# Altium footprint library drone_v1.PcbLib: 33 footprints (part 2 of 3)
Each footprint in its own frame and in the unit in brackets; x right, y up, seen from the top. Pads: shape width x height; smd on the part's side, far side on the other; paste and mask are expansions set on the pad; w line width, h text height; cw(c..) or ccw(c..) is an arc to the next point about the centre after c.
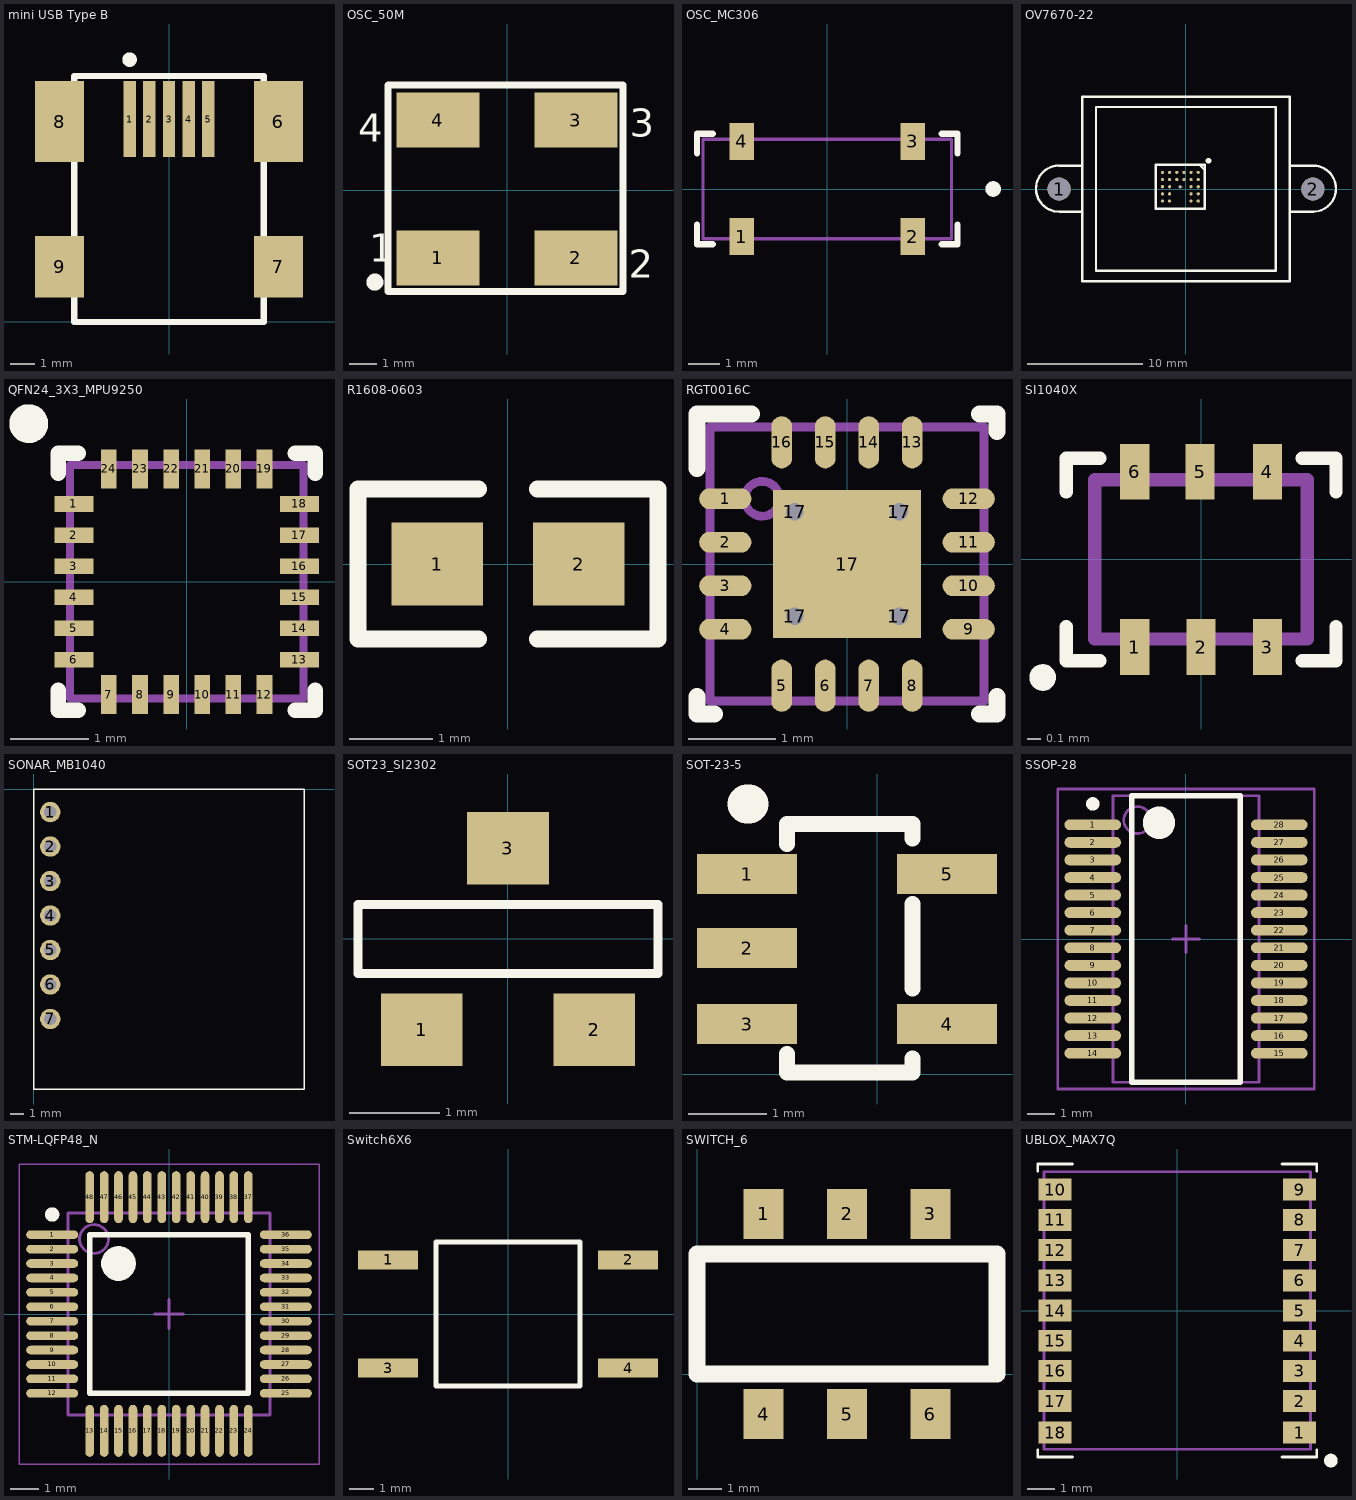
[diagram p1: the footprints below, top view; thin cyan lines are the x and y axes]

## mini USB Type B [mm]
pads (9):
  rect 0.5x3.1 smd: 1(-1.6,8.25) 2(-0.8,8.25) 3(0,8.25) 4(0.8,8.25) 5(1.6,8.25)
  rect 2x3.3 smd: 6(4.45,8.15) 8(-4.45,8.15)
  rect 2x2.5 smd: 7(4.45,2.25) 9(-4.45,2.25)
Top Overlay:
  circle w0.3: c-1.6,10.668 r0.146
  lines w0.254: -3.85,0 -3.85,10 3.85,10 3.85,0 -3.85,0

## OSC_50M [mm] "for 50MHz"
height 3.5
pads (4):
  rect 3x2 smd: 1(-2.515,-2.46) 2(2.489,-2.46) 3(2.485,2.54) 4(-2.515,2.54)
Top Overlay:
  circle w0.5: c-4.801,-3.333 r0.057
  lines w0.254: -4.318,-3.683 -4.318,3.81 4.191,3.81 4.191,-3.683 -4.318,-3.683
  text "1" at -5.004,-2.591 h1.02
  text "2" at 4.394,-3.175 h1.02
  text "3" at 4.445,1.93 h1.02
  text "4" at -5.41,1.753 h1.02

## OSC_MC306 [mm]
pads (4):
  rect 0.8x1.2 smd paste+0 mask+0.05: 1(-2.75,-1.53) 2(2.75,-1.53) 3(2.75,1.53) 4(-2.75,1.53)
Top Overlay:
  circle w0.25: c5.336,0 r0.125
  lines w0.2: -4.191,-1.143 -4.191,-1.778 -3.683,-1.778 ; -4.191,1.143 -4.191,1.778 -3.683,1.778 ; 3.683,-1.778 4.191,-1.778 4.191,-1.143 ; 3.683,1.778 4.191,1.778 4.191,1.143
Mechanical 13:
  lines w0.1: -4,-1.6 -4,1.6 4,1.6 4,-1.6 -4,-1.6

## OV7670-22 [mm]
pads (26):
  round 2 hole 2: 1(-11,0) 2(11,0)
  round 0.28 smd: A1(1.062,1.44) A2(1.062,0.82) A3(1.062,0.2) A4(1.062,-0.42) A5(1.062,-1.04) B1(0.442,1.44) B2(0.442,0.82) B3(0.442,0.2) B4(0.442,-0.42) B5(0.442,-1.04) C1(-0.178,1.44) C2(-0.178,0.82) D1(-0.798,1.44) D2(-0.798,0.82) E1(-1.418,1.44) E2(-1.418,0.82) E3(-1.418,0.2) E4(-1.418,-0.42) E5(-1.418,-1.04) F1(-2.038,1.44) F2(-2.038,0.82) F3(-2.038,0.2) F4(-2.038,-0.42) F5(-2.038,-1.04)
Top Overlay:
  circle w0.25: c1.951,2.454 r0.125
  lines w0.102: -0.632,0.2 -0.327,0.2 ; -0.488,0.068 -0.488,0.347
  lines w0.2: 1.165,2.1 1.637,1.628 ; -2.613,-1.7 1.637,-1.7 1.637,2.1 -2.613,2.1 -2.613,-1.7
  lines w0.203: -9.062,-1.967 -10.977,-1.967 cw(c-11.011,0.032) -11.049,2.032 -9,2.032 ; -7.8,-7.112 -7.8,7.1 ; -7.8,7.112 7.8,7.112 ; -7.788,-7.1 7.788,-7.1 ; 7.8,-7.1 7.8,7.1 ; 9,2.032 11.049,2.032 cw(c11.014,0.032) 11.033,-1.968 9.063,-1.968 ; 9,8 -9,8 -9,-8 9,-8 9,8.001

## QFN24_3X3_MPU9250 [mm]
pads (24):
  rect 0.5x0.2 smd paste+0 mask+0.03: 1(-1.45,1) 2(-1.45,0.6) 3(-1.45,0.2) 4(-1.45,-0.2) 5(-1.45,-0.6) 6(-1.45,-1) 13(1.45,-1) 14(1.45,-0.6) 15(1.45,-0.2) 16(1.45,0.2) 17(1.45,0.6) 18(1.45,1)
  rect 0.2x0.5 smd paste+0 mask+0.03: 7(-1,-1.45) 8(-0.6,-1.45) 9(-0.2,-1.45) 10(0.2,-1.45) 11(0.6,-1.45) 12(1,-1.45) 19(1,1.45) 20(0.6,1.45) 21(0.2,1.45) 22(-0.2,1.45) 23(-0.6,1.45) 24(-1,1.45)
Top Overlay:
  circle w0.25: c-2.03,2.032 r0.125
  lines w0.2: -1.651,-1.397 -1.651,-1.651 -1.397,-1.651 ; -1.651,1.397 -1.651,1.651 -1.397,1.651 ; 1.397,-1.651 1.651,-1.651 1.651,-1.397 ; 1.397,1.651 1.651,1.651 1.651,1.397
Mechanical 13:
  lines w0.1: -1.5,-1.5 0,-1.5 1.5,-1.5 1.5,1.5 -1.5,1.5 -1.5,-1.5

## R1608-0603 [mm]
pads (2):
  rect 1.1x1 smd: 1(-0.85,0) 2(0.85,0)
Top Overlay:
  lines w0.2: -0.35,-0.9 -1.8,-0.9 -1.8,0.9 -0.35,0.9 ; 0.35,-0.9 1.8,-0.9 1.8,0.9 0.35,0.9

## RGT0016C [mm]
pads (21):
  oval 0.6x0.24 smd paste-0.102 mask+0.051: 1(-1.4,0.75) 2(-1.4,0.25) 3(-1.4,-0.25) 4(-1.4,-0.75) 9(1.4,-0.75) 10(1.4,-0.25) 11(1.4,0.25) 12(1.4,0.75)
  oval 0.24x0.6 smd paste-0.102 mask+0.051: 5(-0.75,-1.4) 6(-0.25,-1.4) 7(0.25,-1.4) 8(0.75,-1.4) 13(0.75,1.4) 14(0.25,1.4) 15(-0.25,1.4) 16(-0.75,1.4)
  round 0.5 / inner round 1.524 / far side round 0.5 hole 0.203 mask+0.051: 17(-0.6,-0.6) 17(-0.6,0.6) 17(0.6,-0.6) 17(0.6,0.6)
  rect 1.7x1.7 smd paste-0.837 mask+0.051: 17(0,0)
Top Overlay:
  lines w0.2: -1.725,-1.525 -1.725,-1.725 -1.525,-1.725 ; -1.725,1.1 -1.725,1.725 -1.1,1.725 ; 1.525,-1.725 1.725,-1.725 1.725,-1.525 ; 1.525,1.725 1.725,1.725 1.725,1.525
Top Paste:
  region: -0.774,0.774 -0.774,-0.774 0.774,-0.774 0.774,0.774
Mechanical 1:
  circle w0.1: c-0.975,0.75 r0.2
  lines w0.1: -1.575,-1.575 1.575,-1.575 1.575,1.575 -1.575,1.575 -1.575,-1.575

## SI1040X [mm]
pads (6):
  rect 0.22x0.42 smd paste+0 mask+0.05: 1(-0.5,-0.66) 2(0,-0.66) 3(0.5,-0.66) 4(0.5,0.66) 5(-0.008,0.66) 6(-0.5,0.66)
Top Overlay:
  circle w0.1: c-1.193,-0.889 r0.05
  lines w0.1: -1.016,-0.508 -1.016,-0.762 -0.762,-0.762 ; -1.016,0.508 -1.016,0.762 -0.762,0.762 ; 0.762,-0.762 1.016,-0.762 1.016,-0.508 ; 0.762,0.762 1.016,0.762 1.016,0.508
Mechanical 13:
  lines w0.1: -0.8,-0.6 0.8,-0.6 0.8,0.6 -0.8,0.6 -0.8,-0.6

## SONAR_MB1040 [mm]
pads (7):
  round 1.5 hole 0.9: 1(1.2,-1.7) 2(1.2,-4.24) 3(1.2,-6.78) 4(1.2,-9.32) 5(1.2,-11.86) 6(1.2,-14.4) 7(1.2,-16.94)
Top Overlay:
  lines w0.1: 0,-22.1 19.9,-22.1 19.9,0 0,0 0,-22.1

## SOT23_SI2302 [mm]
pads (3):
  rect 0.9x0.8 smd: 1(-0.95,-1) 2(0.95,-1) 3(0,1)
Top Overlay:
  lines w0.1: -1.651,-0.381 -1.651,0.381 1.651,0.381 1.651,-0.381 -1.651,-0.381

## SOT-23-5 [mil]
pads (5):
  rect 50x20 smd: 1(-65,100) 2(-65,63) 3(-65,25) 4(35,25) 5(35,100)
Top Overlay:
  lines w8: -45,10 -45,0.68 17.76,0.68 17.76,7.76 ; -45,115 -45,125 17.76,125 17.76,117.76 ; 17.76,42.76 17.76,85
  lines w19.68: -65,135 -64,135

## SSOP-28 [mm] "28-Pin SSOP 0.65 mm Pitch"
height 2
pads (28):
  oval 2.1x0.4 smd: 1(-3.45,4.225) 2(-3.45,3.575) 3(-3.45,2.925) 4(-3.45,2.275) 5(-3.45,1.625) 6(-3.45,0.975) 7(-3.45,0.325) 8(-3.45,-0.325) 9(-3.45,-0.975) 10(-3.45,-1.625) 11(-3.45,-2.275) 12(-3.45,-2.925) 13(-3.45,-3.575) 14(-3.45,-4.225) 15(3.45,-4.225) 16(3.45,-3.575) 17(3.45,-2.925) 18(3.45,-2.275) 19(3.45,-1.625) 20(3.45,-0.975) 21(3.45,-0.325) 22(3.45,0.325) 23(3.45,0.975) 24(3.45,1.625) 25(3.45,2.275) 26(3.45,2.925) 27(3.45,3.575) 28(3.45,4.225)
Top Overlay:
  circle w0.25: c-3.45,5 r0.125
  circle w0.6: c-1,4.3 r0.3
  lines w0.2: -2,-5.3 -2,5.3 2,5.3 2,-5.3 -2,-5.3
Mechanical 13:
  circle w0.1: c-1.8,4.4 r0.5
  lines w0.1: -2.7,-5.3 -2.7,5.3 2.7,5.3 2.7,-5.3 -2.7,-5.3
Mechanical 15:
  lines w0.1: -0.5,0 0.5,0 ; 0,-0.5 0,0.5 ; -4.75,-5.55 -4.75,5.55 4.75,5.55 4.75,-5.55 -4.75,-5.55
3D body: height 2, standoff 0, extent -2.7,-5.3 2.7,5.3

## STM-LQFP48_N [mm] "QFP, 48-Leads, Body 7x7mm, Pitch 0.5mm, IPC Medium Density"
height 1.6
pads (48):
  oval 1.8x0.3 smd: 1(-4.05,2.75) 2(-4.05,2.25) 3(-4.05,1.75) 4(-4.05,1.25) 5(-4.05,0.75) 6(-4.05,0.25) 7(-4.05,-0.25) 8(-4.05,-0.75) 9(-4.05,-1.25) 10(-4.05,-1.75) 11(-4.05,-2.25) 12(-4.05,-2.75) 25(4.05,-2.75) 26(4.05,-2.25) 27(4.05,-1.75) 28(4.05,-1.25) 29(4.05,-0.75) 30(4.05,-0.25) 31(4.05,0.25) 32(4.05,0.75) 33(4.05,1.25) 34(4.05,1.75) 35(4.05,2.25) 36(4.05,2.75)
  oval 0.3x1.8 smd: 13(-2.75,-4.05) 14(-2.25,-4.05) 15(-1.75,-4.05) 16(-1.25,-4.05) 17(-0.75,-4.05) 18(-0.25,-4.05) 19(0.25,-4.05) 20(0.75,-4.05) 21(1.25,-4.05) 22(1.75,-4.05) 23(2.25,-4.05) 24(2.75,-4.05) 37(2.75,4.05) 38(2.25,4.05) 39(1.75,4.05) 40(1.25,4.05) 41(0.75,4.05) 42(0.25,4.05) 43(-0.25,4.05) 44(-0.75,4.05) 45(-1.25,4.05) 46(-1.75,4.05) 47(-2.25,4.05) 48(-2.75,4.05)
Top Overlay:
  circle w0.6: c-1.75,1.75 r0.3
  circle w0.25: c-4.05,3.45 r0.125
  lines w0.2: -2.75,-2.75 2.75,-2.75 2.75,2.75 -2.75,2.75 -2.75,-2.75
Mechanical 13:
  circle w0.1: c-2.6,2.6 r0.5
  lines w0.1: -3.5,-3.5 3.5,-3.5 3.5,3.5 -3.5,3.5 -3.5,-3.5
Mechanical 15:
  lines w0.05: -5.2,-5.2 5.2,-5.2 5.2,5.2 -5.2,5.2 -5.2,-5.2
  lines w0.1: -0.5,0 0.5,0 ; 0,-0.5 0,0.5
3D body: height 1.6, standoff 0.05, extent -3.5,-3.5 3.5,3.5

## Switch6X6 [mm]
pads (4):
  rect 2.5x0.8 smd: 1(-5,2.25) 2(5,2.25) 3(-5,-2.25) 4(5,-2.25)
Top Overlay:
  lines w0.2: -3,-3 3,-3 3,3 -3,3 -3,-3

## SWITCH_6 [mm]
pads (6):
  rect 1.2x1.5 smd: 1(2,4.8) 2(4.5,4.8) 3(7,4.8) 4(2,-1.2) 5(4.5,-1.2) 6(7,-1.2)
Top Overlay:
  lines w0.508: 0,0 0,3.6 9,3.6 9,0 0,0

## UBLOX_MAX7Q [mm]
pads (18):
  rect 1.2x0.8 smd paste+0 mask+0.05: 1(4.45,-4.44) 2(4.45,-3.3) 3(4.45,-2.2) 4(4.45,-1.1) 5(4.45,0) 6(4.45,1.1) 7(4.45,2.2) 8(4.45,3.3) 9(4.45,4.4) 10(-4.45,4.4) 11(-4.45,3.3) 12(-4.45,2.2) 13(-4.45,1.1) 14(-4.45,0) 15(-4.45,-1.1) 16(-4.45,-2.2) 17(-4.45,-3.3) 18(-4.45,-4.44)
Top Overlay:
  circle w0.25: c5.59,-5.461 r0.125
  lines w0.1: -5.08,-5.08 -5.08,-5.334 -3.81,-5.334 ; -5.08,5.08 -5.08,5.334 -3.81,5.334 ; 3.81,-5.334 5.08,-5.334 5.08,-5.08 ; 3.81,5.334 5.08,5.334 5.08,5.08
Mechanical 13:
  lines w0.1: -4.85,-5.05 4.85,-5.05 4.85,5.05 -4.85,5.05 -4.85,-5.05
